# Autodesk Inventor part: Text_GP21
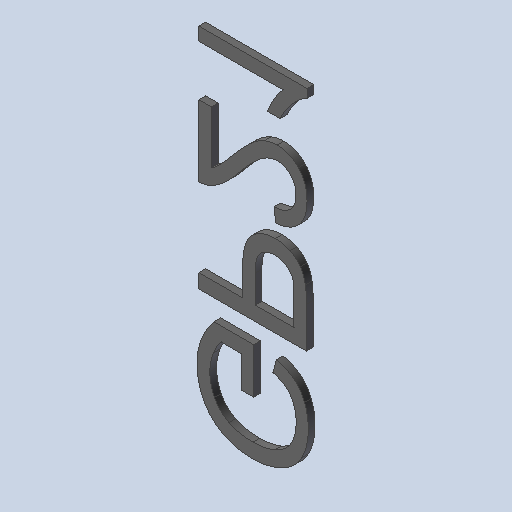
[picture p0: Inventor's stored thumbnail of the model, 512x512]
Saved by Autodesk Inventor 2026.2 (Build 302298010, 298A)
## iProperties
Created: 2026-10
Part Number: Text_GP21
Material: Générique
Document SubType Name: Modeling
Designer: mel
Density: 1 g/cm^3
Appearance: Par défaut
Author: mel
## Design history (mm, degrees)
feature "Base1"
feature "Base2"
feature "Base3"
feature "Base4"
node "Solide1"
node "Solide2"
node "Solide3"
node "Solide4"
